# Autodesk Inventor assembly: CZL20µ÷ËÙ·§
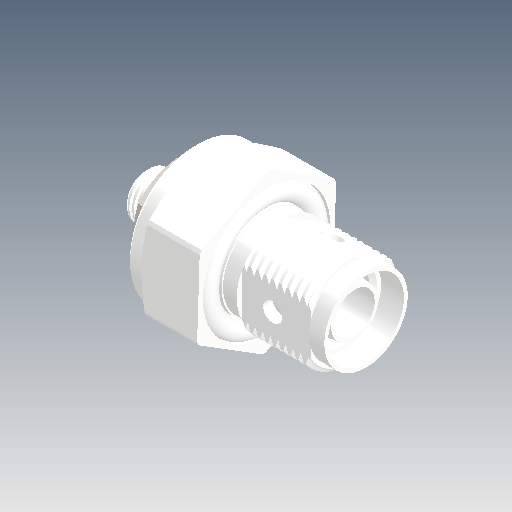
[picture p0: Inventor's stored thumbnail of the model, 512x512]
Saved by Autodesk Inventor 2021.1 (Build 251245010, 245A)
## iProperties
Created: 2021-05
Part Number: CZL20µ÷ËÙ·§
Document SubType Name: Assembly
Designer: user
Author: user
Revision Number: ÈÎºÎ
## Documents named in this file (4)
- D:\Vault_2016\Projekty\Clamptek\Hydraulic\CHLC\CHLC-50\Inventor\CHLC-FAMT50L\CZL20µ÷ËÙ·§.iam
- D:\Vault_2016\Projekty\Clamptek\Hydraulic\CHLC\CHLC-50\Inventor\CHLC-FAMT50L\20·§Ìå_1.ipt
- D:\Vault_2016\Projekty\Clamptek\Hydraulic\CHLC\CHLC-50\Inventor\CHLC-FAMT50L\20µ÷ËÙ¸Ë_1.ipt
- D:\Vault_2016\Projekty\Clamptek\Hydraulic\CHLC\CHLC-50\Inventor\CHLC-FAMT50L\hex thin nuts-grades ab-chamfered gb(GB_FASTENER_NUT_STNAB M6-S)_1.ipt
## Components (3 placed, 3 different names)
1. 20·§Ìå_1_20
2. 20µ÷ËÙ¸Ë_1_21
3. hex thin nuts-grades ab-chamfered gb(GB_FASTENER_NUT_STNAB M6-S)_1_22
